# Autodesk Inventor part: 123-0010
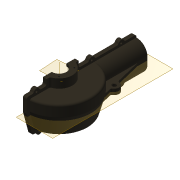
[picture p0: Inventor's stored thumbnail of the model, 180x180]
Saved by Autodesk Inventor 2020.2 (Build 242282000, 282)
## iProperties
Created: 2006-02
Part Number: 123-0010
Document SubType Name: Modeling
Designer: F.Stasiak
Description: Obudowa - prawa
Material: L450
Project: Przekładnia X51
Mass: 3378.52 g
Surface Area: 1383.42 cm^2
Volume: 466.003 cm^3
Density: 7.25 g/cm^3
Appearance: Brąz armatni (nowy/polerowany)
Manager: www.cadconsulting.pl
Company: Fabian Stasiak CAD Consulting
Author: F.Stasiak
Subject: Zbiór ćwiczeń. Autodesk Inventor 2020. Kurs podstawowy
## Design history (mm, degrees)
sketch "Szkic1"
  geometry: L1 (0, -90)-(0, 90); A1 r 90 centre (0, 0) between (0, -90) and (0, 90); 2 further points
  constraints: 2 end point, 2 midpoint, 2 point on circle, 1 centre point, 1 coincident, 1 vertical, 1 other
  dimensions: "d0" = 90 radius of A1
extrude "Wyciągnięcie proste1" new body sketch "Szkic1" distance "d1" = 80; taper "d2" = 0 deg
node "Płaszczyzna konstrukcyjna4"
feature "Podział1"
feature "Szkic powierzchni2" dims angle "d38" = 15 deg
sketch "Szkic3"
  geometry: L1 (-78, 290)-(0, 290); L2 (0, 290)-(0, 150); L3 (0, 150)-(-78, 150); L4 (-78, 150)-(-78, 290); L5 (0, 0)-(0, 180) reference; L6 (34.5, 90)-(-126.5, 90) reference
  constraints: 10 end point, 2 horizontal, 2 parallel, 1 collinear, 1 perpendicular, 2 other
  dimensions: "d7" = 78 distance of L2.end L3.end; "d8" = 140 distance of L1.end L2.end; "d9" = 60 distance between parallel lines of L6 L3
extrude "Wyciągnięcie proste3" join sketch "Szkic3" distance "d10" = 40; taper "d11" = 0 deg
fillet "Zaokrąglenie1" dims "d12" = 30
node "Oś konstrukcyjna1"
feature "Skorupa1" dims "d13" = 5
sketch "Szkic4"
  geometry: L1 (2, 196.603)-(80, 196.603); L2 (80, 196.603)-(80, 156.603); L3 (80, 156.603)-(2, 156.603); L4 (2, 156.603)-(2, 196.603); L5 (80, -13.397)-(80, 276.603) reference; L6 (2, 153.741)-(2, 276.603) reference; L7 (2, 246.603)-(80, 246.603); L8 (80, 246.603)-(80, 276.603); L9 (80, 276.603)-(2, 276.603); L10 (2, 276.603)-(2, 246.603); L11 (2, 276.603)-(80, 276.603) reference
  constraints: 16 end point, 5 collinear, 4 parallel, 2 horizontal, 2 perpendicular
  dimensions: "d14" = 40 distance of L1.end L2.end; "d15" = 30 distance between parallel lines of L9 L7; "d16" = 50 distance between parallel lines of L1 L7
extrude "Wyciągnięcie proste4" join sketch "Szkic4" stored distance "d17" = 30; taper "d18" = 0 deg
node "Płaszczyzna konstrukcyjna1"
sketch "Szkic5"
  geometry: C1 r 27.5 at (0, -22.5) reference
extrude "Wyciągnięcie proste5" cut sketch "Szkic5" distance "d19" = 25; taper "d20" = 0 deg
node "Płaszczyzna konstrukcyjna2"
sketch "Szkic6"
  geometry: C1 r 23.5 at (0, -18) reference
extrude "Wyciągnięcie proste6" cut sketch "Szkic6" extent not by distance; stored distance "d21" = 12; taper "d22" = 0 deg
sketch "Szkic7"
  geometry: C1 r 18.1 at (0, 33.423) reference; C2 r 22.5 at (0, 33.423)
  constraints: 1 centre point, 1 coincident
  dimensions: "d23" = 45 diameter of C2
extrude "Wyciągnięcie proste7" cut sketch "Szkic7" stored distance "d24" = 12; taper "d25" = 0 deg
sketch "Szkic8"
  geometry: C1 r 23.5 at (0, 34.577) reference; C2 r 20 at (0, 34.577)
  constraints: 1 centre point, 1 coincident
  dimensions: "d26" = 40 diameter of C2
extrude "Wyciągnięcie proste8" cut sketch "Szkic8" extent not by distance; stored distance "d27" = 12; taper "d28" = 0 deg
sketch "Szkic9"
  geometry: L1 (80, 76.603)-(104, 76.603); L2 (104, 76.603)-(104, 40.603); L3 (104, 40.603)-(80, 40.603); L4 (80, 40.603)-(80, 76.603); L5 (104.002, 76.603)-(-8, 76.603) reference; L6 (80, -13.397)-(80, 276.603) reference
  constraints: 8 end point, 2 collinear, 2 parallel, 1 horizontal, 1 perpendicular
  dimensions: "d29" = 24 distance of L2.end L3.end; "d30" = 36 distance of L1.end L2.end
revolve "Obrót1" sketch "Szkic9" stored, may be unused: angle "d31" = 180 deg
node "Płaszczyzna konstrukcyjna3"
sketch "Szkic10"
  geometry: C1 r 23.5 at (0, -18) reference
extrude "Wyciągnięcie proste9" cut sketch "Szkic10" stored distance "d32" = 10; taper "d33" = 0 deg
sketch "Szkic12"
  geometry: C1 r 27.5 at (28.723, -80); A1 r 23.5 centre (28.723, -80) between (28.723, -56.5) and (28.723, -103.5) reference
  constraints: 1 centre point, 1 coincident
  dimensions: "d39" = 4 radial gap between concentric circles of A1 C1
extrude "Wyciągnięcie proste11" cut sketch "Szkic12" distance "d40" = 6; taper "d41" = 0 deg
sketch "Szkic13"
  geometry: L1 (0, 76.603)-(0, -76.603) reference; A1 r 36 centre (0, 0) between (0, 36) and (0, -36) reference
extrude "Wyciągnięcie proste12" join sketch "Szkic13" distance "d42" = 20; taper "d43" = 0 deg
node "Płaszczyzna konstrukcyjna5"
sketch "Szkic14"
  geometry: C1 r 23.5 at (0, -18) reference
extrude "Wyciągnięcie proste13" cut sketch "Szkic14" stored distance "d44" = 20; taper "d45" = 0 deg
sketch "Szkic16"
  geometry: C1 r 20 at (0, 18); A1 r 11 centre (0, 18) between (9.927, 22.739) and (7.275, 26.251) reference
  constraints: 1 centre point
  dimensions: "d49" = 40 diameter of C1
extrude "Wyciągnięcie proste15" cut sketch "Szkic16" extent not by distance; stored distance "d50" = 20; taper "d51" = 0 deg
sketch "Szkic17"
  geometry: C1 r 20 at (0, 18); A1 r 20 centre (0, 18) between (-1.231, -1.962) and (1.231, 37.962) reference
  constraints: 1 centre point, 1 coincident, 1 concentric
extrude "Wyciągnięcie proste16" cut sketch "Szkic17" extent not by distance; stored distance "d52" = 20; taper "d53" = 0 deg
sketch "Szkic18"
  geometry: L1 (-2, -113.138)-(-2, -153.741) reference; L2 (48, -167.138)-(-2, -153.741) reference; L3 (78, -167.138)-(48, -167.138) reference; L4 (78, -167.138)-(78, -113.138) reference; L5 (102, -113.138)-(78, -113.138) reference; L6 (-2, -113.138)-(-22, -113.138) reference; L7 (102, -121.138)-(86, -121.138); L8 (86, -121.138)-(86, -175.138); L9 (86, -175.138)-(46.947, -175.138); L10 (46.947, -175.138)-(-10, -159.88); L11 (-10, -159.88)-(-10, -121.138); L12 (-10, -121.138)-(-22, -121.138); L13 (102, -111.138)-(76, -111.138); L14 (76, -111.138)-(76, -165.138); L15 (76, -165.138)-(48.263, -165.138); L16 (48.263, -165.138)-(0, -152.206); L17 (0, -152.206)-(0, -111.138); L18 (0, -111.138)-(-22, -111.138); L19 (-22, -121.138)-(-22, -111.138); L20 (102, -121.138)-(102, -111.138)
  constraints: 28 end point, 1 parallel, 1 perpendicular, 10 other
  dimensions: "d54" = 8 distance between parallel lines of L6 L12; "d55" = 10 distance between parallel lines of L18 L12
extrude "Wyciągnięcie proste17" join sketch "Szkic18" distance "d56" = 10; taper "d57" = 0 deg
sketch "Szkic19"
  geometry: L1 (-2, -41.138)-(-22, -41.138) reference; L2 (-2, -0.536)-(-2, -41.138) reference; L3 (0, 0)-(0, 122.862) reference; L4 (78, -41.138)-(102, -41.138) reference; L5 (78, -41.138)-(78, 122.862) reference; L6 (-22, -33.138)-(-10, -33.138); L7 (-10, -33.138)-(-10, -0.536); L8 (-10, 0)-(-10, 122.862); L9 (102, -34.138)-(85, -34.138); L10 (85, -34.138)-(85, 122.862); L11 (-10, -0.536)-(-10, 0); L12 (0, -0.536)-(0, -43.138); L13 (0, -43.138)-(-22, -43.138); L14 (0, 0)-(0, 122.862); L15 (0, -0.536)-(0, 0); L16 (-22, -43.138)-(-22, -33.138); L17 (0, 122.862)-(-10, 122.862); L18 (102, -44.138)-(75, -44.138); L19 (75, -44.138)-(75, 122.862); L20 (102, -44.138)-(102, -34.138); L21 (75, 122.862)-(85, 122.862)
  constraints: 32 end point, 5 perpendicular, 3 collinear, 2 parallel, 4 other
  dimensions: "d58" = 8 distance between parallel lines of L6 L1; "d59" = 10 distance between parallel lines of L13 L6; "d60" = 7 distance between parallel lines of L9 L4; "d61" = 10 distance between parallel lines of L18 L9
extrude "Wyciągnięcie proste18" join sketch "Szkic19" distance "d62" = 10; taper "d63" = 0 deg
sketch "Szkic20"
  geometry: L1 (-58.658, 2.259)-(-58.658, 41) reference; L2 (-58.658, 129)-(-58.658, 285) reference; L3 (36.342, 128)-(36.342, 285) reference; L4 (37.342, 41)-(37.342, -13) reference; C1 r 8 at (-58.658, 21.629); C2 r 8 at (-58.658, 165); C3 r 8 at (-58.658, 245); C4 r 8 at (37.342, 14); C5 r 8 at (36.342, 164); C6 r 8 at (36.342, 244); 1 further point
  constraints: 6 centre point, 5 equal radius, 4 point on line, 2 midpoint, 1 coincident
  dimensions: "d64" = 16 diameter of C1; "d65" = 80 distance of C3.centre C2.centre; "d66" = 36 distance of C2.centre L2.start; "d67" = 80 distance of C6.centre C5.centre; "d68" = 36 distance of L3.start C5.centre
extrude "Wyciągnięcie proste19" join sketch "Szkic20" distance "d69" = 10; taper "d70" = 0 deg
fillet "Zaokrąglenie2" dims "d71" = 5
fillet "Zaokrąglenie3" dims "d72" = 5
fillet "Zaokrąglenie4" dims "d73" = 5
fillet "Zaokrąglenie5" dims "d74" = 5
sketch "Szkic21"
  geometry: A1 r 8 centre (-15, 40) between (-18.077, 47.385) and (-18.077, 32.615) reference; A2 r 8 centre (-15, -40) between (-18.077, -32.615) and (-18.077, -47.385) reference; A3 r 8 centre (-15, -183.371) between (-18.077, -175.986) and (-18.077, -190.755) reference; A4 r 8 centre (81, -191) between (84.077, -198.385) and (84.077, -183.615) reference; A5 r 8 centre (80, 39) between (83.077, 31.615) and (83.077, 46.385) reference; A6 r 8 centre (80, -41) between (83.077, -48.385) and (83.077, -33.615) reference
hole "Otwór1" sketch "Szkic21" at (-15, -183.371), (-15, -40), (-15, 40), (80, 39), (80, -41), (81, -191) diameter "d77" = 5.5; stored, may be unused: countersink angle "d81" = 90 deg, drill point angle "d83" = 118 deg; dims "d78" = 6, "d79" = 4, "d80" = 2, "d82" = 8
node "Płaszczyzna konstrukcyjna6"
sketch "Szkic22"
  geometry: L1 (-1.034, -22.661)-(29.062, -146.052)
  constraints: 2 end point
feature "Żebro1" sketch "Szkic22" dims "d84" = 1, "d85" = 15
sketch "Szkic23"
  geometry: L1 (-30.326, -26.891)-(0, 97.446) reference; C1 r 12.5 at (-20.269, 14.345); A1 r 20 centre (40, -75.655) between (40, -55.655) and (40, -95.655) reference
  constraints: 1 centre point, 1 point on line
  dimensions: "d87" = 25 diameter of C1; "d88" = 90 vertical distance of A1.centre C1.centre
extrude "Wyciągnięcie proste21" join sketch "Szkic23" stored distance "d92" = 10; taper "d93" = 0 deg
fillet "Zaokrąglenie8" dims "d94" = 5
sketch "Szkic24"
  geometry: A1 r 12.5 centre (-20.269, 14.345) between (-20.9, 26.829) and (-26.577, 3.553) reference
hole "Otwór2" sketch "Szkic24" at (-20.269, 14.345) diameter "d95" = 10; stored, may be unused: countersink angle "d99" = 90 deg, drill point angle "d101" = 118 deg; dims "d96" = 6, "d97" = 4, "d98" = 2, "d100" = 8
chamfer "Faza1" distance "d102" = 1; stored, may be unused: second distance "d103" = 2, angle "d104" = 45 deg
sketch "Szkic25"
  geometry: C1 r 2.75 at (-20.86, 20.86) reference; C2 r 2.75 at (-20.86, -20.86) reference
  constraints: 1 centre point, 2 other
hole "Otwór3" sketch "Szkic25" at (-20.86, 20.86), (-20.86, -20.86) diameter "d105" = 4.134; stored, may be unused: countersink angle "d109" = 90 deg, drill point angle "d111" = 118 deg; dims "d106" = 8, "d107" = 4, "d108" = 2, "d110" = 12
sketch "Szkic26"
  geometry: C1 r 2.75 at (20.86, -20.86) reference; C2 r 2.75 at (20.86, 20.86) reference
  constraints: 2 centre point, 4 other
hole "Otwór4" sketch "Szkic26" at (20.86, -20.86), (20.86, 20.86) diameter "d112" = 4.134; stored, may be unused: countersink angle "d116" = 90 deg, drill point angle "d118" = 118 deg; dims "d113" = 8, "d114" = 4, "d115" = 2, "d117" = 12
sketch "Szkic27"
  geometry: C1 r 3 at (-17.019, 31.404) reference; C2 r 3 at (-17.019, -14.558) reference
  constraints: 2 centre point, 4 other
hole "Otwór5" sketch "Szkic27" at (-17.019, 31.404), (-17.019, -14.558) diameter "d119" = 4.134; stored, may be unused: countersink angle "d123" = 90 deg, drill point angle "d125" = 118 deg; dims "d120" = 8, "d121" = 4, "d122" = 2, "d124" = 12
node "Bryła1"
node "Korpusy bryłowe"
node "Korpusy powierzchniowe"
node "Odniesienie1"
node "Odniesienie2"
node "Odniesienie3"
node "Odniesienie4"
node "Odniesienie5"
node "Odniesienie6"
node "Odniesienie8"
